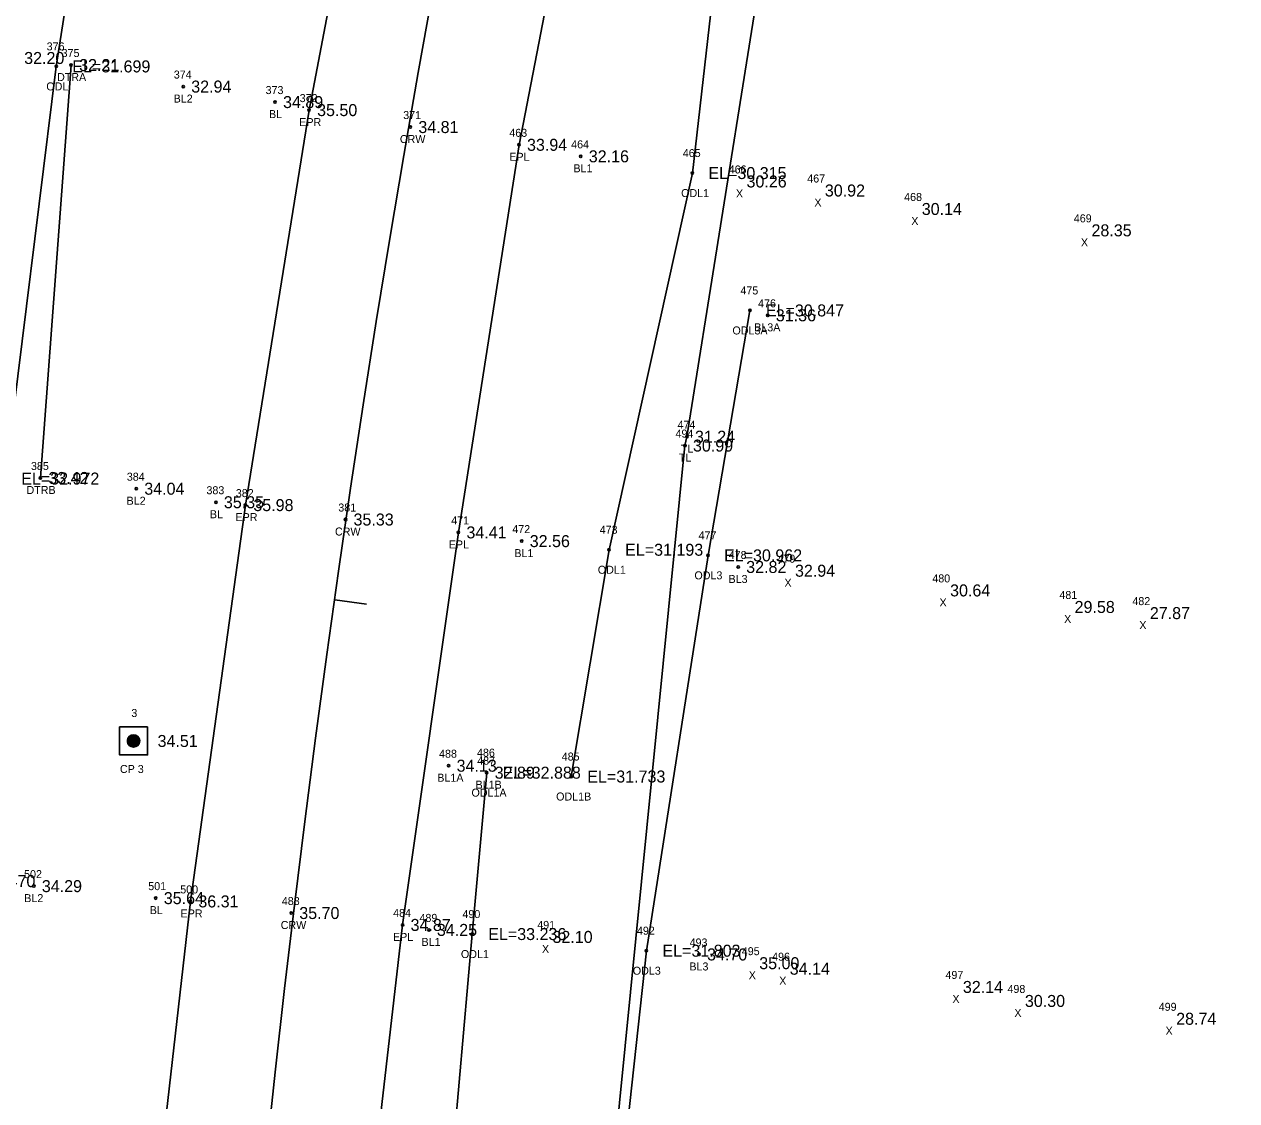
# Model space of a CAD drawing. Extents: x 2042117 to 2045853, y 303080 to 309569.
# Drawn here: x 2042820 to 2042971.5, y 307553.4 to 307687.9 of the extents above; entities that cross this region are included whole.
import ezdxf

# ---------------------------------------------------------------- set-up
doc = ezdxf.new("R2010")
doc.units = 0
for name, color, linetype in [('RD_DTM_BkLn_txCode', 7, 'Continuous'), ('RD_EX_H2O', 7, 'Continuous'), ('RD_EX_H2O_txCode', 7, 'Continuous'), ('RD_EX_Misc_txCode', 7, 'Continuous'), ('RD_EX_Road', 7, 'Continuous'), ('RD_EX_Road_txCode', 7, 'Continuous'), ('RD_EX_TX_H2O_ELEV', 7, 'Continuous'), ('RD_EX_TX_Misc_ELEV', 7, 'Continuous'), ('RD_EX_TX_Road_ELEV', 7, 'Continuous'), ('RD_EX_TX_VEG_ELEV', 7, 'Continuous'), ('RD_EX_VEG', 7, 'Continuous'), ('RD_EX_VEG_txCode', 7, 'Continuous'), ('RD_HC_Cl', 7, 'Continuous'), ('RD_HC_Data_Tic', 7, 'Continuous'), ('RD_HC_Survey', 7, 'Continuous'), ('RD_HC_Survey_ELEV', 7, 'Continuous'), ('RD_HC_Survey_txCode', 7, 'Continuous'), ('RD_SMD_Locator', 7, 'Continuous')]:
    doc.layers.add(name, color=color, linetype=linetype)

msp = doc.modelspace()

# ---------------------------------------------------------------- linework, layer by layer
at = {"layer": 'RD_EX_H2O'}
msp.add_line((2042825.83, 307682.85), (2042821.99, 307631.24), dxfattribs=at)
for points in [[(2043129.27, 308428.82), (2043103.11, 308386.53), (2043087.59, 308358.52), (2043078.21, 308342.14), (2043052.09, 308299.16), (2043025.98, 308255.36), (2043015.05, 308240.46), (2043007.57, 308236.11), (2042996.98, 308213.48), (2042981.31, 308163.04), (2042956.15, 308118.86), (2042936.41, 308071.81), (2042918.77, 308024.43), (2042903.29, 307975.96), (2042886.4, 307928.42), (2042872.04, 307879.53), (2042857.18, 307831.23), (2042843.33, 307782.22), (2042831.48, 307730.99), (2042823.97, 307682.68), (2042817.59, 307631.17), (2042809.6, 307580.86), (2042807.78, 307554.78)], [(2042954.71, 307908), (2042941.87, 307861.24), (2042931.11, 307813.3), (2042918.51, 307765.02), (2042908.96, 307717.68), (2042903.47, 307669.35), (2042893.06, 307622.27), (2042888.33, 307593.93)], [(2042910.65, 307652.18), (2042905.42, 307621.57), (2042897.72, 307572.16), (2042892.26, 307522.14), (2042886.65, 307473.55), (2042887.85, 307426.41), (2042886.57, 307414.7)], [(2042877.76, 307594.41), (2042875.95, 307574.24), (2042871.62, 307524.91), (2042871.88, 307474.1), (2042865.43, 307427.05), (2042866.84, 307378.87)]]:
    msp.add_lwpolyline(points, dxfattribs=at)
at = {"layer": 'RD_EX_Road'}
for points in [[(2043150.45, 308415.87), (2043123.31, 308373.62), (2043097.1, 308331.18), (2043072.09, 308287.75), (2043048.26, 308243.82), (2043025.59, 308198.98), (2043003.92, 308153.61), (2042983.57, 308107.75), (2042964.45, 308061.45), (2042946.64, 308015.14), (2042930.05, 307967.71), (2042914.65, 307920.21), (2042900.21, 307872.25), (2042887.2, 307823.91), (2042875.38, 307775.02), (2042864.88, 307726.03), (2042855.57, 307677.22), (2042847.6, 307627.85), (2042840.73, 307578.32), (2042835.07, 307528.58), (2042830.98, 307478.6), (2042828.36, 307428.87), (2042826.99, 307378.91)], [(2043172.79, 308402.16), (2043145.1, 308359.37), (2043119.63, 308317.71), (2043094.79, 308274.94), (2043071.92, 308232.51), (2043049.11, 308188.03), (2043027.82, 308142.81), (2043007.75, 308097.66), (2042989.09, 308052.53), (2042971.66, 308006.7), (2042955.42, 307960.12), (2042939.67, 307912.41), (2042925.65, 307865.09), (2042912.69, 307817.39), (2042901.29, 307769.38), (2042891.09, 307720.95), (2042881.8, 307672.88), (2042874.23, 307624.44), (2042867.25, 307575.38), (2042861.55, 307525.78), (2042857.62, 307475.83), (2042855.03, 307427.78), (2042853.64, 307379.19)]]:
    msp.add_lwpolyline(points, dxfattribs=at)
at = {"layer": 'RD_EX_VEG'}
msp.add_lwpolyline([(2043048.7, 308112.2), (2043032.62, 308087.68), (2043027.55, 308080.82), (2043013.5, 308043.09), (2042994.71, 307997.39), (2042983.47, 307967.75), (2042952.97, 307870.73), (2042935.66, 307809.47), (2042918.92, 307737.74), (2042902.79, 307636.4), (2042902.54, 307635.29), (2042891, 307519.21), (2042885.61, 307482.85), (2042881.1, 307379.92)], dxfattribs=at)
at = {"layer": 'RD_HC_Cl'}
msp.add_arc((2044751.25, 307348.43), 1911.29, 137.68184, 219.86836, dxfattribs=at)
at = {"layer": 'RD_HC_Data_Tic'}
msp.add_line((2042858.78, 307616.01), (2042862.74, 307615.45), dxfattribs=at)
at = {"layer": 'RD_HC_Survey'}
for p, q in [((2042832.88, 307598.19), (2042832.88, 307598.55)), ((2042832.91, 307598.11), (2042832.91, 307598.63)), ((2042832.93, 307598.05), (2042832.93, 307598.69)), ((2042832.96, 307598), (2042832.96, 307598.74)), ((2042832.98, 307597.96), (2042832.98, 307598.78)), ((2042833.01, 307597.92), (2042833.01, 307598.82)), ((2042833.03, 307597.89), (2042833.03, 307598.85)), ((2042833.06, 307597.86), (2042833.06, 307598.88)), ((2042833.08, 307597.83), (2042833.08, 307598.91)), ((2042833.11, 307597.81), (2042833.11, 307598.93)), ((2042833.13, 307597.79), (2042833.13, 307598.96)), ((2042833.15, 307597.77), (2042833.15, 307598.98)), ((2042833.18, 307597.75), (2042833.18, 307599)), ((2042833.2, 307597.73), (2042833.2, 307599.01)), ((2042833.23, 307597.72), (2042833.23, 307599.03)), ((2042833.25, 307597.7), (2042833.25, 307599.04)), ((2042833.28, 307597.69), (2042833.28, 307599.06)), ((2042833.3, 307597.68), (2042833.3, 307599.07)), ((2042833.33, 307597.66), (2042833.33, 307599.08)), ((2042833.35, 307597.65), (2042833.35, 307599.09)), ((2042833.38, 307597.65), (2042833.38, 307599.1)), ((2042833.4, 307597.64), (2042833.4, 307599.11)), ((2042833.43, 307597.63), (2042833.43, 307599.11)), ((2042833.45, 307597.62), (2042833.45, 307599.12)), ((2042833.48, 307597.62), (2042833.48, 307599.13)), ((2042833.5, 307597.61), (2042833.5, 307599.13)), ((2042833.53, 307597.61), (2042833.53, 307599.13)), ((2042833.55, 307597.61), (2042833.55, 307599.14)), ((2042833.58, 307597.6), (2042833.58, 307599.14)), ((2042833.6, 307597.6), (2042833.6, 307599.14)), ((2042833.62, 307597.6), (2042833.62, 307599.14)), ((2042833.65, 307597.6), (2042833.65, 307599.14)), ((2042833.67, 307597.6), (2042833.67, 307599.14)), ((2042833.7, 307597.61), (2042833.7, 307599.14)), ((2042833.72, 307597.61), (2042833.72, 307599.14)), ((2042833.75, 307597.61), (2042833.75, 307599.13)), ((2042833.77, 307597.62), (2042833.77, 307599.13)), ((2042833.8, 307597.62), (2042833.8, 307599.12)), ((2042833.82, 307597.63), (2042833.82, 307599.12)), ((2042833.85, 307597.63), (2042833.85, 307599.11)), ((2042833.87, 307597.64), (2042833.87, 307599.1)), ((2042833.9, 307597.65), (2042833.9, 307599.09)), ((2042833.92, 307597.66), (2042833.92, 307599.08)), ((2042833.95, 307597.67), (2042833.95, 307599.07)), ((2042833.97, 307597.68), (2042833.97, 307599.06)), ((2042834, 307597.69), (2042834, 307599.05)), ((2042834.02, 307597.71), (2042834.02, 307599.04)), ((2042834.05, 307597.72), (2042834.05, 307599.02)), ((2042834.07, 307597.74), (2042834.07, 307599)), ((2042834.1, 307597.76), (2042834.1, 307598.99)), ((2042834.12, 307597.78), (2042834.12, 307598.97)), ((2042834.14, 307597.8), (2042834.14, 307598.94)), ((2042834.17, 307597.82), (2042834.17, 307598.92)), ((2042834.19, 307597.85), (2042834.19, 307598.9)), ((2042834.22, 307597.88), (2042834.22, 307598.87)), ((2042834.24, 307597.91), (2042834.24, 307598.84)), ((2042834.27, 307597.94), (2042834.27, 307598.8)), ((2042834.29, 307597.98), (2042834.29, 307598.76)), ((2042834.32, 307598.03), (2042834.32, 307598.72)), ((2042834.34, 307598.08), (2042834.34, 307598.66)), ((2042834.37, 307598.15), (2042834.37, 307598.59)), ((2042834.39, 307598.26), (2042834.39, 307598.48))]:
    msp.add_line(p, q, dxfattribs=at)
msp.add_lwpolyline([(2042835.38, 307600.12), (2042831.88, 307600.12), (2042831.88, 307596.62), (2042835.38, 307596.62)], close=True, dxfattribs=at)
msp.add_circle((2042833.63, 307598.37), 0.769, dxfattribs=at)
at = {"layer": 'RD_SMD_Locator'}
for centre in [(2042825.83, 307682.85), (2042823.97, 307682.68), (2042839.84, 307680.16), (2042851.31, 307678.22), (2042855.57, 307677.22), (2042868.22, 307675.1), (2042881.8, 307672.88), (2042889.52, 307671.44), (2042903.47, 307669.35), (2042910.65, 307652.18), (2042912.89, 307651.57), (2042902.79, 307636.4), (2042902.54, 307635.29), (2042821.99, 307631.24), (2042833.97, 307629.9), (2042843.92, 307628.21), (2042847.6, 307627.85), (2042860.12, 307626.05), (2042874.23, 307624.44), (2042882.14, 307623.35), (2042893.06, 307622.27), (2042905.42, 307621.57), (2042909.19, 307620.12), (2042833.63, 307598.37), (2042873, 307595.28), (2042877.76, 307594.41), (2042877.76, 307594.41), (2042888.33, 307593.93), (2042821.17, 307580.23), (2042836.41, 307578.73), (2042840.73, 307578.32), (2042853.34, 307576.87), (2042867.25, 307575.38), (2042870.54, 307574.76), (2042875.95, 307574.24), (2042897.72, 307572.16), (2042904.3, 307571.69)]:
    msp.add_circle(centre, 0.15, dxfattribs=at)

# ---------------------------------------------------------------- texts
at = {"layer": 'RD_DTM_BkLn_txCode'}
for s, p in [('374', (2042838.66, 307681.16)), ('373', (2042850.13, 307679.22)), ('BL2', (2042838.64, 307678.16)), ('BL', (2042850.56, 307676.22)), ('464', (2042888.32, 307672.44)), ('BL1', (2042888.6, 307669.44)), ('476', (2042911.68, 307652.57)), ('BL3A', (2042911.19, 307649.57)), ('384', (2042832.79, 307630.9)), ('383', (2042842.74, 307629.21)), ('BL2', (2042832.76, 307627.9)), ('BL', (2042843.17, 307626.21)), ('472', (2042880.96, 307624.35)), ('BL1', (2042881.22, 307621.35)), ('478', (2042908.01, 307621.12)), ('BL3', (2042907.98, 307618.12)), ('488', (2042871.81, 307596.28)), ('487', (2042876.58, 307595.41)), ('BL1A', (2042871.59, 307593.28)), ('BL1B', (2042876.37, 307592.41)), ('502', (2042819.95, 307581.23)), ('501', (2042835.47, 307579.73)), ('BL2', (2042819.97, 307578.23)), ('BL', (2042835.65, 307576.73)), ('489', (2042869.36, 307575.76)), ('BL1', (2042869.62, 307572.76)), ('493', (2042903.12, 307572.69)), ('BL3', (2042903.09, 307569.69))]:
    msp.add_text(s, height=1, dxfattribs=at).set_placement(p)
at = {"layer": 'RD_EX_H2O_txCode'}
for s, p in [('376', (2042822.77, 307684.68)), ('375', (2042824.64, 307683.85)), ('DTRA', (2042824.07, 307680.85)), ('ODL', (2042822.73, 307679.68)), ('465', (2042902.27, 307671.35)), ('ODL1', (2042902.06, 307666.35)), ('475', (2042909.47, 307654.18)), ('ODL3A', (2042908.47, 307649.18)), ('385', (2042820.81, 307632.24)), ('DTRB', (2042820.25, 307629.24)), ('473', (2042891.88, 307624.27)), ('477', (2042904.24, 307623.57)), ('ODL1', (2042891.65, 307619.27)), ('ODL3', (2042903.72, 307618.57)), ('486', (2042876.55, 307596.41)), ('485', (2042887.14, 307595.93)), ('ODL1A', (2042875.86, 307591.41)), ('ODL1B', (2042886.44, 307590.93)), ('490', (2042874.73, 307576.24)), ('492', (2042896.54, 307574.16)), ('ODL1', (2042874.54, 307571.24)), ('ODL3', (2042896.02, 307569.16))]:
    msp.add_text(s, height=1, dxfattribs=at).set_placement(p)
at = {"layer": 'RD_EX_Misc_txCode'}
for s, p in [('466', (2042908, 307669.3)), ('467', (2042917.82, 307668.17)), ('X', (2042908.91, 307666.3)), ('468', (2042929.93, 307665.86)), ('X', (2042918.71, 307665.17)), ('X', (2042930.82, 307662.86)), ('469', (2042951.13, 307663.19)), ('X', (2042952.02, 307660.19)), ('479', (2042914.1, 307620.65)), ('X', (2042914.97, 307617.65)), ('480', (2042933.45, 307618.19)), ('481', (2042949.33, 307616.12)), ('482', (2042958.45, 307615.35)), ('X', (2042934.35, 307615.19)), ('X', (2042949.92, 307613.12)), ('X', (2042959.32, 307612.35)), ('491', (2042884.08, 307574.88)), ('X', (2042884.67, 307571.88)), ('495', (2042909.64, 307571.6)), ('496', (2042913.43, 307570.91)), ('X', (2042910.51, 307568.6)), ('497', (2042935.09, 307568.63)), ('X', (2042914.32, 307567.91)), ('498', (2042942.84, 307566.88)), ('X', (2042935.96, 307565.63)), ('X', (2042943.7, 307563.88)), ('499', (2042961.74, 307564.65)), ('X', (2042962.6, 307561.65))]:
    msp.add_text(s, height=1, dxfattribs=at).set_placement(p)
at = {"layer": 'RD_EX_Road_txCode'}
for s, p in [('372', (2042854.39, 307678.22)), ('EPR', (2042854.34, 307675.22)), ('463', (2042880.59, 307673.88)), ('EPL', (2042880.59, 307670.88)), ('382', (2042846.41, 307628.85)), ('EPR', (2042846.37, 307625.85)), ('471', (2042873.33, 307625.44)), ('EPL', (2042873.02, 307622.44)), ('500', (2042839.47, 307579.32)), ('EPR', (2042839.51, 307576.32)), ('484', (2042866.07, 307576.38)), ('EPL', (2042866.05, 307573.38))]:
    msp.add_text(s, height=1, dxfattribs=at).set_placement(p)
at = {"layer": 'RD_EX_TX_H2O_ELEV'}
for s, p in [('EL=31.699', (2042825.97, 307681.93)), ('32.21', (2042826.83, 307682.1)), ('EL=30.315', (2042905.47, 307668.6)), ('EL=30.847', (2042912.65, 307651.43)), ('EL=32.972', (2042819.59, 307630.42)), ('33.42', (2042822.99, 307630.49)), ('EL=31.193', (2042895.06, 307621.52)), ('EL=30.962', (2042907.42, 307620.82)), ('EL=32.888', (2042879.76, 307593.66)), ('EL=31.733', (2042890.33, 307593.18)), ('EL=33.470', (2042811.6, 307580.11)), ('EL=33.236', (2042877.95, 307573.49)), ('EL=31.803', (2042899.72, 307571.41))]:
    msp.add_text(s, height=1.5, dxfattribs=at).set_placement(p)
at = {"layer": 'RD_EX_TX_Misc_ELEV'}
for s, p in [('32.20', (2042819.96, 307682.98)), ('32.94', (2042840.84, 307679.41)), ('34.89', (2042852.31, 307677.47)), ('32.16', (2042890.52, 307670.69)), ('30.26', (2042910.23, 307667.55)), ('30.92', (2042920.02, 307666.42)), ('30.14', (2042932.13, 307664.11)), ('28.35', (2042953.34, 307661.44)), ('31.36', (2042913.89, 307650.82)), ('34.04', (2042834.97, 307629.15)), ('35.35', (2042844.92, 307627.46)), ('32.56', (2042883.14, 307622.6)), ('32.82', (2042910.19, 307619.37)), ('32.94', (2042916.29, 307618.9)), ('30.64', (2042935.67, 307616.44)), ('29.58', (2042951.23, 307614.37)), ('27.87', (2042960.63, 307613.6)), ('34.13', (2042874, 307594.53)), ('32.89', (2042878.76, 307593.66)), ('34.29', (2042822.17, 307579.48)), ('35.64', (2042837.41, 307577.98)), ('34.25', (2042871.54, 307574.01)), ('32.10', (2042885.98, 307573.13)), ('34.70', (2042905.3, 307570.94)), ('35.00', (2042911.82, 307569.85)), ('34.14', (2042915.63, 307569.16)), ('32.14', (2042937.27, 307566.88)), ('30.30', (2042945.02, 307565.13)), ('28.74', (2042963.92, 307562.9))]:
    msp.add_text(s, height=1.5, dxfattribs=at).set_placement(p)
at = {"layer": 'RD_EX_TX_Road_ELEV'}
for s, p in [('35.50', (2042856.57, 307676.47)), ('33.94', (2042882.8, 307672.13)), ('35.98', (2042848.6, 307627.1)), ('34.41', (2042875.23, 307623.69)), ('36.31', (2042841.73, 307577.57)), ('34.87', (2042868.25, 307574.63))]:
    msp.add_text(s, height=1.5, dxfattribs=at).set_placement(p)
at = {"layer": 'RD_EX_TX_VEG_ELEV'}
for s, p in [('30.99', (2042903.54, 307634.54)), ('31.24', (2042903.79, 307635.65))]:
    msp.add_text(s, height=1.5, dxfattribs=at).set_placement(p)
at = {"layer": 'RD_EX_VEG_txCode'}
for s, p in [('474', (2042901.61, 307637.4)), ('494', (2042901.36, 307636.29)), ('TL', (2042902.02, 307634.4)), ('TL', (2042901.77, 307633.29))]:
    msp.add_text(s, height=1, dxfattribs=at).set_placement(p)
at = {"layer": 'RD_HC_Survey_ELEV'}
for s, p in [('34.81', (2042869.22, 307674.35)), ('35.33', (2042861.12, 307625.3)), ('34.51', (2042836.63, 307597.62)), ('35.70', (2042854.34, 307576.12))]:
    msp.add_text(s, height=1.5, dxfattribs=at).set_placement(p)
at = {"layer": 'RD_HC_Survey_txCode'}
for s, p in [('371', (2042867.33, 307676.1)), ('CRW', (2042866.91, 307673.1)), ('381', (2042859.22, 307627.05)), ('CRW', (2042858.8, 307624.05)), ('3', (2042833.35, 307601.37)), ('CP 3', (2042831.93, 307594.37)), ('483', (2042852.16, 307577.87)), ('CRW', (2042852.02, 307574.87))]:
    msp.add_text(s, height=1, dxfattribs=at).set_placement(p)

doc.saveas('drawing.dxf')
